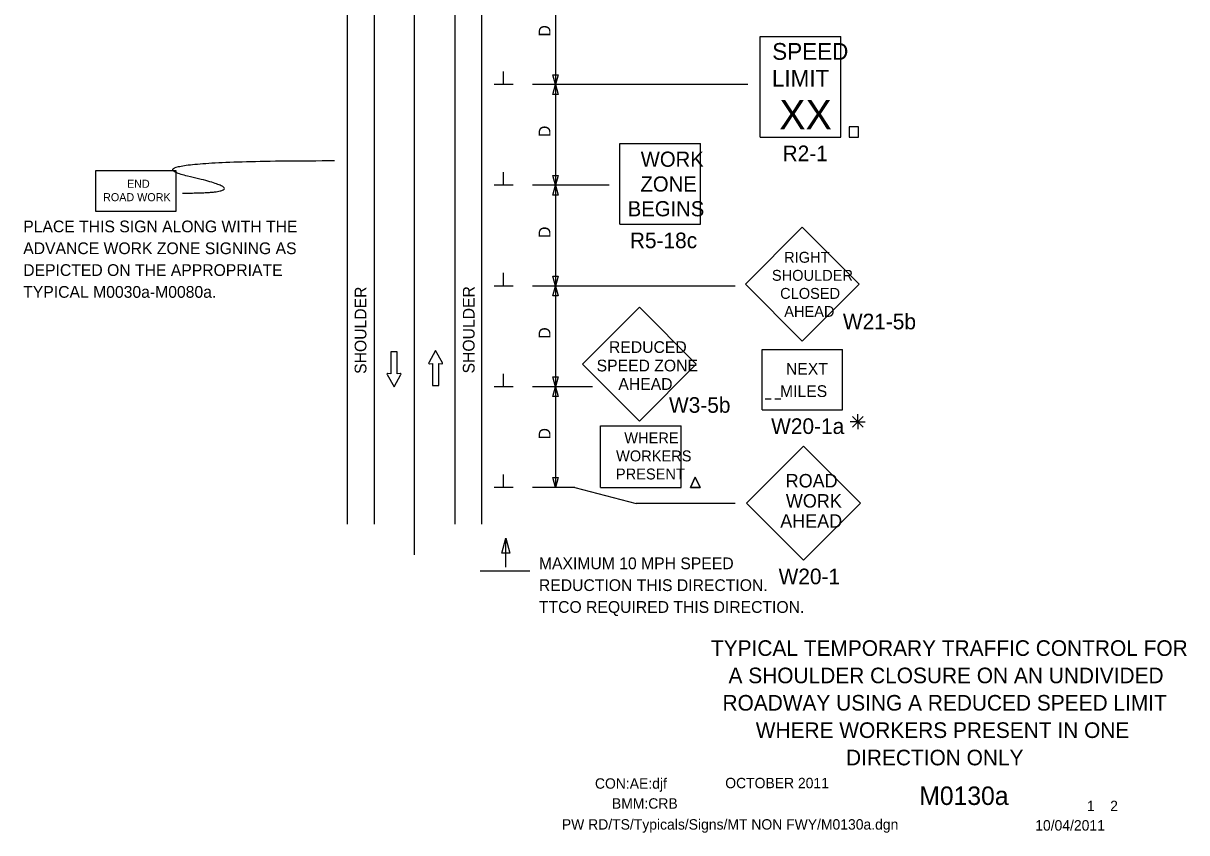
# Model space of a CAD drawing. Extents: x 16750 to 18472, y 7218 to 8205.
# Drawn here: x 16750 to 17443, y 7218 to 7700 of the extents above; entities that cross this region are included whole.
import ezdxf

# ---------------------------------------------------------------- set-up
doc = ezdxf.new("R2010")
doc.units = 0
for name, color, linetype in [('BORDER', 7, 'Continuous'), ('BORDER_SIGNAL_WO', 7, 'Continuous'), ('Level 3', 7, 'Continuous'), ('Level 6', 7, 'Continuous'), ('MT_SCRATCH_LEVEL_E', 7, 'Continuous'), ('PAVT_EDGE_EX', 7, 'Continuous'), ('TRAFFIC_SIGNS_PR', 7, 'Continuous'), ('TYPICAL_TEXT_DIMEN_PR', 7, 'Continuous')]:
    doc.layers.add(name, color=color, linetype=linetype)

msp = doc.modelspace()

# ---------------------------------------------------------------- linework, layer by layer
at = {"layer": 'Level 3'}
for p, q in [((17035.27, 7384.69), (17037.62, 7393.48)), ((17037.62, 7376.36), (17037.62, 7393.48)), ((17037.62, 7393.48), (17039.98, 7384.69)), ((17037.62, 7384.69), (17035.27, 7384.69)), ((17039.98, 7384.69), (17037.62, 7384.69)), ((17051.8, 7373.86), (17022.36, 7373.86))]:
    msp.add_line(p, q, dxfattribs=at)
at = {"layer": 'Level 6'}
for p, q in [((17117.13, 7531.18), (17083.19, 7497.24)), ((17151.07, 7497.24), (17117.13, 7531.18)), ((17083.19, 7497.24), (17117.13, 7463.3)), ((17117.13, 7463.3), (17151.07, 7497.24)), ((17094.03, 7460.44), (17142.03, 7460.44)), ((17094.03, 7423.79), (17094.03, 7460.44)), ((17142.03, 7423.79), (17142.03, 7460.44)), ((17094.03, 7423.79), (17142.03, 7423.79))]:
    msp.add_line(p, q, dxfattribs=at)
msp.add_lwpolyline([(17242.1, 7632.42), (17247.69, 7632.42), (17247.69, 7638.59), (17242.1, 7638.59)], close=True, dxfattribs=at)
for points in [[(17150.47, 7429.96), (17147.67, 7423.79)], [(17147.67, 7423.79), (17150.47, 7429.96)], [(17153.27, 7423.79), (17150.47, 7429.96)], [(17150.47, 7429.96), (17153.27, 7423.79)], [(17147.67, 7423.79), (17153.27, 7423.79)], [(17153.27, 7423.79), (17147.67, 7423.79)]]:
    msp.add_lwpolyline(points, dxfattribs=at)
at = {"layer": 'MT_SCRATCH_LEVEL_E'}
for p, q in [((16972.86, 7504.62), (16969.12, 7504.62)), ((16969.12, 7504.62), (16969.12, 7491.36)), ((16972.86, 7504.62), (16969.12, 7504.62)), ((16969.12, 7504.62), (16969.12, 7491.36)), ((16972.86, 7491.36), (16972.86, 7504.62)), ((16972.86, 7491.36), (16972.86, 7504.62)), ((16995.75, 7505.28), (16991.64, 7498.04)), ((16995.75, 7505.28), (16991.64, 7498.04)), ((16999.89, 7498.04), (16995.75, 7505.28)), ((16999.89, 7498.04), (16995.75, 7505.28)), ((16969.12, 7491.36), (16967.34, 7491.68)), ((16969.12, 7491.36), (16967.34, 7491.68)), ((16974.64, 7491.68), (16972.86, 7491.36)), ((16974.64, 7491.68), (16972.86, 7491.36)), ((16992.12, 7497.35), (16993.9, 7497.67)), ((16992.12, 7497.35), (16993.9, 7497.67)), ((16993.9, 7497.67), (16993.9, 7484.41)), ((16993.9, 7497.67), (16993.9, 7484.41)), ((16997.64, 7484.41), (16997.64, 7497.67)), ((16997.64, 7497.67), (16999.42, 7497.35)), ((16997.64, 7484.41), (16997.64, 7497.67)), ((16997.64, 7497.67), (16999.42, 7497.35)), ((16966.86, 7490.99), (16971.01, 7483.75)), ((16966.86, 7490.99), (16971.01, 7483.75)), ((16971.01, 7483.75), (16975.12, 7490.99)), ((16971.01, 7483.75), (16975.12, 7490.99)), ((16993.9, 7484.41), (16997.64, 7484.41)), ((16993.9, 7484.41), (16997.64, 7484.41))]:
    msp.add_line(p, q, dxfattribs=at)
for centre, start, end in [((16967.27, 7491.22), 80.03619, 209.77312), ((16967.27, 7491.22), 80.03619, 209.77312), ((16974.71, 7491.22), 330.42484, 99.96381), ((16974.71, 7491.22), 330.42484, 99.96381), ((16992.04, 7497.81), 150.42484, 279.96381), ((16992.04, 7497.81), 150.42484, 279.96381), ((16999.48, 7497.81), 260.03619, 29.77312), ((16999.48, 7497.81), 260.03619, 29.77312)]:
    msp.add_arc(centre, 0.463, start, end, dxfattribs=at)
at = {"layer": 'PAVT_EDGE_EX'}
for p, q in [((16983.15, 7383.56), (16983.15, 8180.56)), ((16943.15, 8137.01), (16943.15, 7401.86)), ((16959.15, 8137.01), (16959.15, 7401.86)), ((17007.15, 8137.01), (17007.15, 7401.86)), ((17023.15, 8137.01), (17023.15, 7401.86))]:
    msp.add_line(p, q, dxfattribs=at)
for points in [[(16983.15, 7601.86), (16983.15, 7626.86)], [(16983.15, 7501.86), (16983.15, 7526.86)], [(16983.15, 7401.86), (16983.15, 7426.86)]]:
    msp.add_lwpolyline(points, dxfattribs=at)
at = {"layer": 'TRAFFIC_SIGNS_PR'}
for p, q in [((17189.08, 7692.42), (17237.08, 7692.42)), ((17189.08, 7632.42), (17189.08, 7692.42)), ((17237.08, 7632.42), (17237.08, 7692.42)), ((17189.08, 7632.42), (17237.08, 7632.42)), ((17105.46, 7580.58), (17105.46, 7628.58)), ((17105.46, 7628.58), (17153.46, 7628.58)), ((17153.46, 7580.58), (17153.46, 7628.58)), ((17105.46, 7580.58), (17153.46, 7580.58)), ((17214.2, 7578.81), (17180.26, 7544.87)), ((17248.14, 7544.87), (17214.2, 7578.81)), ((17180.26, 7544.87), (17214.2, 7510.93)), ((17214.2, 7510.93), (17248.14, 7544.87)), ((17190.2, 7469.93), (17190.2, 7505.93)), ((17190.2, 7505.93), (17238.2, 7505.93)), ((17238.2, 7469.93), (17238.2, 7505.93)), ((17192.06, 7476.53), (17195.56, 7476.53)), ((17197.86, 7476.53), (17201.36, 7476.53)), ((17190.2, 7469.93), (17238.2, 7469.93)), ((17214.86, 7448.3), (17180.92, 7414.36)), ((17248.8, 7414.36), (17214.86, 7448.3)), ((17180.92, 7414.36), (17214.86, 7380.42)), ((17214.86, 7380.42), (17248.8, 7414.36))]:
    msp.add_line(p, q, dxfattribs=at)
msp.add_lwpolyline([(16793.2, 7588.35), (16841.2, 7588.35), (16841.2, 7612.35), (16793.2, 7612.35)], close=True, dxfattribs=at)
msp.add_open_spline([(16845.07, 7599.1), (16892.31, 7599.1), (16807.28, 7618.45), (16935.57, 7618.45)], degree=2, dxfattribs=at)
at = {"layer": 'TYPICAL_TEXT_DIMEN_PR'}
for p, q in [((17067.15, 7723.75), (17067.15, 7664.3)), ((17036.27, 7663.75), (17036.27, 7671.54)), ((17067.15, 7663.75), (17065.58, 7669.61)), ((17065.58, 7669.61), (17067.15, 7669.61)), ((17067.15, 7669.61), (17068.73, 7669.61)), ((17068.73, 7669.61), (17067.15, 7663.75)), ((17041.89, 7663.75), (17030.64, 7663.75)), ((17181.69, 7663.75), (17053.58, 7663.75)), ((17065.58, 7657.89), (17067.15, 7663.75)), ((17067.15, 7663.75), (17068.73, 7657.89)), ((17067.15, 7663.75), (17067.15, 7603.75)), ((17067.15, 7657.89), (17065.58, 7657.89)), ((17068.73, 7657.89), (17067.15, 7657.89)), ((17036.27, 7603.75), (17036.27, 7611.54)), ((17067.15, 7603.75), (17065.58, 7609.61)), ((17065.58, 7609.61), (17067.15, 7609.61)), ((17067.15, 7609.61), (17068.73, 7609.61)), ((17068.73, 7609.61), (17067.15, 7603.75)), ((17041.89, 7603.75), (17030.64, 7603.75)), ((17099.21, 7603.75), (17053.58, 7603.75)), ((17065.58, 7597.89), (17067.15, 7603.75)), ((17067.15, 7603.75), (17068.73, 7597.89)), ((17067.15, 7603.75), (17067.15, 7543.82)), ((17067.15, 7597.89), (17065.58, 7597.89)), ((17068.73, 7597.89), (17067.15, 7597.89)), ((17036.27, 7543.75), (17036.27, 7551.54)), ((17067.15, 7543.75), (17065.58, 7549.61)), ((17065.58, 7549.61), (17067.15, 7549.61)), ((17067.15, 7549.61), (17068.73, 7549.61)), ((17068.73, 7549.61), (17067.15, 7543.75)), ((17041.89, 7543.75), (17030.64, 7543.75)), ((17174.16, 7543.75), (17053.58, 7543.75)), ((17065.58, 7537.89), (17067.15, 7543.75)), ((17067.15, 7543.75), (17068.73, 7537.89)), ((17067.15, 7543.75), (17067.15, 7483.75)), ((17067.15, 7537.89), (17065.58, 7537.89)), ((17068.73, 7537.89), (17067.15, 7537.89)), ((17036.27, 7483.75), (17036.27, 7491.54)), ((17067.15, 7483.75), (17065.58, 7489.61)), ((17065.58, 7489.61), (17067.15, 7489.61)), ((17067.15, 7489.61), (17068.73, 7489.61)), ((17068.73, 7489.61), (17067.15, 7483.75)), ((17041.89, 7483.75), (17030.64, 7483.75)), ((17089.28, 7483.75), (17053.58, 7483.75)), ((17065.58, 7477.89), (17067.15, 7483.75)), ((17067.15, 7477.89), (17065.58, 7477.89)), ((17067.15, 7483.75), (17068.73, 7477.89)), ((17067.15, 7483.75), (17067.15, 7423.75)), ((17068.73, 7477.89), (17067.15, 7477.89)), ((17244.07, 7466.12), (17250.44, 7459.74)), ((17250.44, 7466.12), (17244.07, 7459.74)), ((17247.26, 7462.93), (17247.26, 7467.39)), ((17247.26, 7462.93), (17242.72, 7462.93)), ((17247.26, 7462.93), (17250.44, 7462.93)), ((17247.26, 7462.93), (17251.73, 7462.93)), ((17247.26, 7462.93), (17247.26, 7458.43)), ((17036.27, 7423.75), (17036.27, 7431.54)), ((17067.15, 7423.75), (17065.58, 7429.61)), ((17065.58, 7429.61), (17067.15, 7429.61)), ((17067.15, 7429.61), (17068.73, 7429.61)), ((17068.73, 7429.61), (17067.15, 7423.75)), ((17041.89, 7423.75), (17030.64, 7423.75)), ((17078.66, 7423.75), (17053.58, 7423.75)), ((17078.66, 7423.75), (17115.24, 7414.14)), ((17174.16, 7414.14), (17115.24, 7414.14))]:
    msp.add_line(p, q, dxfattribs=at)

# ---------------------------------------------------------------- texts
at = {"layer": 'BORDER'}
for s, p in [('TYPICAL TEMPORARY TRAFFIC CONTROL FOR', (17159.78, 7323.44)), ('A SHOULDER CLOSURE ON AN UNDIVIDED', (17170.25, 7307.14)), ('ROADWAY USING A REDUCED SPEED LIMIT', (17166.65, 7290.84)), ('WHERE WORKERS PRESENT IN ONE ', (17186.48, 7274.54)), ('DIRECTION ONLY', (17240.22, 7258.24))]:
    msp.add_text(s, height=9.3, dxfattribs=at).set_placement(p)
at = {"layer": 'BORDER_SIGNAL_WO'}
for s, height, p in [('CON:AE:djf', 6.2, (17090.69, 7244.31)), ('    OCTOBER 2011    ', 6.2, (17159.08, 7244.59)), ('    M0130a    ', 11, (17267.53, 7234.63)), ('BMM:CRB   ', 6.2, (17100.81, 7232.42)), (' 1    2 ', 6.2, (17381.45, 7230.95)), ('PW RD/TS/Typicals/Signs/MT NON FWY/M0130a.dgn     ', 6.2, (17070.98, 7219.96)), ('10/04/2011    ', 6.2, (17352.93, 7219.38))]:
    msp.add_text(s, height=height, dxfattribs=at).set_placement(p)
at = {"layer": 'Level 3'}
for s, p in [('MAXIMUM 10 MPH SPEED', (17057.31, 7375.06)), ('REDUCTION THIS DIRECTION.', (17057.31, 7362.06)), ('TTCO REQUIRED THIS DIRECTION.', (17057.31, 7349.06))]:
    msp.add_text(s, height=7, dxfattribs=at).set_placement(p)
at = {"layer": 'Level 6'}
for s, height, p in [('REDUCED', 7, (17099.04, 7503.88)), ('SPEED ZONE', 7, (17091.69, 7492.88)), ('AHEAD', 7, (17104.65, 7481.88)), ('W3-5b', 9.3, (17134.78, 7468.24))]:
    msp.add_text(s, height=height, dxfattribs=at).set_placement(p)
at = {"layer": 'TRAFFIC_SIGNS_PR'}
for s, height, p in [('SPEED', 10, (17196.29, 7678.49)), ('LIMIT', 10, (17196.09, 7662.49)), ('XX', 17.538, (17200.48, 7637.11)), ('WORK', 9.021, (17117.96, 7614.79)), ('R2-1', 9.3, (17202.43, 7618.12)), ('END', 4.789, (16811.95, 7602.26)), ('ZONE', 9.021, (17117.81, 7600.03)), ('ROAD WORK', 4.789, (16797.71, 7594.28)), ('BEGINS', 9.021, (17110.22, 7585.27)), ('PLACE THIS SIGN ALONG WITH THE', 7, (16750.14, 7575.74)), ('R5-18c', 9.3, (17111.47, 7566.28)), ('ADVANCE WORK ZONE SIGNING AS', 7, (16750.14, 7562.74)), ('RIGHT', 6.5, (17203.36, 7557.61)), ('DEPICTED ON THE APPROPRIATE', 7, (16750.14, 7549.74)), ('SHOULDER', 6.5, (17196.09, 7546.86)), ('TYPICAL M0030a-M0080a.', 7, (16750.14, 7536.74)), ('CLOSED', 6.5, (17200.97, 7536.11)), ('AHEAD', 6.5, (17203.42, 7525.36)), ('W21-5b', 9.3, (17238.38, 7517.95)), ('NEXT', 7, (17204.46, 7490.94)), ('   MILES', 7, (17193.12, 7477.64)), ('W20-1a', 9.3, (17195.63, 7455.63)), ('WHERE', 6.5, (17108.17, 7450.04)), ('WORKERS', 6.5, (17103.27, 7439.29)), ('PRESENT', 6.5, (17103.18, 7428.54)), ('ROAD', 8, (17204.29, 7423.78)), ('WORK', 8, (17204.42, 7411.78)), ('AHEAD', 8, (17201.06, 7399.78)), ('W20-1', 9.3, (17200.07, 7366.12))]:
    msp.add_text(s, height=height, dxfattribs=at).set_placement(p)
at = {"layer": 'TYPICAL_TEXT_DIMEN_PR'}
for s, p in [('D', (17064.19, 7692.36)), ('D', (17064.19, 7632.49)), ('D', (17064.19, 7572.37)), ('SHOULDER', (16954.55, 7491.41)), ('SHOULDER', (17019, 7491.67)), ('D', (17064.19, 7512.37)), ('D', (17064.19, 7452.37))]:
    msp.add_text(s, height=7, rotation=90, dxfattribs=at).set_placement(p)

doc.saveas('drawing.dxf')
